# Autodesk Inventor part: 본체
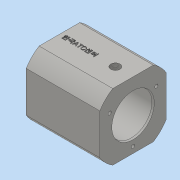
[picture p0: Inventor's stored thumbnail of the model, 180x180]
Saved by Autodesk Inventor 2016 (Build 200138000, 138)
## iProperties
Created: 2020-02
Part Number: 본체
Material: Generic
Document SubType Name: Modeling
Designer: Administrator
Density: 1 g/cm^3
Appearance: Default
Author: Administrator
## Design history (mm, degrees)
sketch "스케치1"
  geometry: C1 r 37.5 at (0, 0); 1 further point
  constraints: 1 centre point, 1 coincident
  dimensions: "d0" = 75 diameter of C1
extrude "돌출1" new body sketch "스케치1" distance "d1" = 71; taper "d2" = 0 deg
sketch "스케치2"
  geometry: L1 (32, -32)-(-32, -32); L2 (-32, -32)-(-32, 32); L3 (-32, 32)-(32, 32); L4 (32, 32)-(32, -32); L5 (32, -32)-(-32, 32); L6 (-32, -32)-(32, 32); L7 (32, 32)-(-32, 32); L8 (-32, 32)-(-32, 47); L9 (-32, 47)-(32, 47); L10 (32, 47)-(32, 32); L11 (-32, -32)-(-47, -32); L12 (-47, -32)-(-47, 32); L13 (-47, 32)-(-32, 32); L14 (-32, 32)-(-32, -32); L15 (-32, -32)-(32, -32); L16 (32, -32)-(32, -47); L17 (32, -47)-(-32, -47); L18 (-32, -47)-(-32, -32); L19 (32, -32)-(47, -32); L20 (47, -32)-(47, 32); L21 (47, 32)-(32, 32); L22 (32, 32)-(32, -32); 1 further point
  constraints: 44 end point, 10 parallel, 5 horizontal, 5 perpendicular, 4 point on line, 2 midpoint
  dimensions: "d3" = 64 distance of L2.end L3.end; "d4" = 64 distance of L1.end L2.end; "d5" = 15 distance of L7.end L8.end; "d6" = 15 distance of L12.end L13.end; "d7" = 15 distance of L15.end L16.end; "d8" = 15 distance of L21.end L20.end
extrude "돌출2" cut sketch "스케치2" stored distance "d9" = 71; taper "d10" = 0 deg
sketch "스케치3"
  geometry: C1 r 14 at (0, 0); 1 further point
  constraints: 1 centre point, 1 coincident
  dimensions: "d11" = 28 diameter of C1
extrude "돌출3" join sketch "스케치3" distance "d12" = 12; taper "d13" = 0 deg
chamfer "모따기1" distance "d14" = 1; stored, may be unused: second distance "d15" = 2, angle "d16" = 45 deg
sketch "스케치4"
  geometry: C1 r 20 at (0, 0); 1 further point
  constraints: 1 centre point, 1 coincident
  dimensions: "d17" = 40 diameter of C1
extrude "돌출4" cut sketch "스케치4" distance "d18" = 62; taper "d19" = 0 deg
sketch "스케치5"
  geometry: 2 further points
  constraints: 1 coincident
hole "구멍1" sketch "스케치5" at (0, 0) diameter "d20" = 8.917; stored, may be unused: countersink angle "d24" = 90 deg, drill point angle "d26" = 118 deg; dims "d21" = 14, "d22" = 4, "d23" = 2, "d25" = 17
sketch "스케치6"
  geometry: C1 r 2 at (0, 0); 1 further point
  constraints: 1 centre point, 1 coincident
  dimensions: "d27" = 4 diameter of C1
extrude "돌출5" cut sketch "스케치6" distance "d28" = 62; taper "d29" = 0 deg
sketch "스케치7" dims "d30" = 52
  geometry: L1 (0, 0)-(0, -26); C1 r 2 at (0, 0) reference; 3 further points
  constraints: 2 coincident, 2 end point, 1 vertical, 1 vertical alignment, 2 other
hole "구멍2" sketch "스케치7" at (0, -26) diameter "d31" = 3.242; stored, may be unused: countersink angle "d35" = 90 deg, drill point angle "d37" = 118 deg; dims "d32" = 10, "d33" = 4, "d34" = 2, "d36" = 12
sketch "스케치8" dims "d41" = 52
  geometry: L1 (0, 0)-(13, -22.517); L2 (0, 0)-(26, 0); C1 r 2 at (0, 0) reference; 3 further points
  constraints: 4 end point, 2 coincident, 1 equal length, 1 horizontal, 3 other
  dimensions: "d42" = 60 deg angle of L1 L2
hole "구멍4" sketch "스케치8" at (13, -22.517) diameter "d53" = 3.242; stored, may be unused: countersink angle "d57" = 90 deg, drill point angle "d59" = 118 deg; dims "d54" = 10, "d55" = 4, "d56" = 2, "d58" = 12
sketch "스케치10"
  geometry: L1 (-71, 19.551)-(-54, 19.551); 1 further point
  constraints: 2 end point, 1 coincident, 1 horizontal
  dimensions: "d63" = 17 distance of L1.start L1.end
hole "구멍5" sketch "스케치10" at (-54, 19.551) diameter "d64" = 8.917; stored, may be unused: countersink angle "d68" = 90 deg, drill point angle "d70" = 118 deg; dims "d65" = 6, "d66" = 4, "d67" = 2, "d69" = 9
sketch "스케치11"
  geometry: C1 r 4.458 at (-54, 19.551) reference; 2 further points
  constraints: 1 coincident
hole "구멍6" sketch "스케치11" at (-54, 19.551) diameter "d71" = 4; stored, may be unused: countersink angle "d75" = 90 deg, drill point angle "d77" = 118 deg; dims "d72" = 6, "d73" = 4, "d74" = 2, "d76" = 20
sketch "스케치12"
  geometry: L1 (-71, 19.551)-(0, 19.551); L2 (0, 0)-(0, 39.102) reference; 1 further point
  constraints: 2 end point, 1 midpoint, 1 other
  dimensions: "d78" = 20 distance from line of L2 point (-20, 19.551); "d79" = 0 distance from line of L1 point (-20, 19.551)
feature "엠보싱1" sketch "스케치12" dims "d3" = 64, "d4" = 64, "d5" = 15, "d6" = 15, "d7" = 15, "d8" = 15, "d80" = 0.5, "d81" = 0
chamfer "모따기2" distance "d82" = 1.8; stored, may be unused: second distance "d83" = 2, angle "d84" = 15 deg
node "솔리드1"
pattern_circular "원형 패턴1" dims angle "d39" = 360 deg
pattern_circular "원형 패턴3" dims angle "d61" = 360 deg
